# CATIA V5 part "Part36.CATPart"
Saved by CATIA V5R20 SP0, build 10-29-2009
Part number: VA 161320-5
Revision: ANY
Definition: UNKNOWN
Nomenclature: VA 161320-5
Source: Unknown
Bounding box of the stored display mesh (mm): x -6.5 to 6.5, y 0 to 4.2, z -6.337 to 6.337
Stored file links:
  C:\Users\Utente\Desktop\IO LAVORO\3D X SITO CF\CUMSA\3D files VA\VA 201720\Part36.CATPart
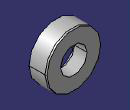
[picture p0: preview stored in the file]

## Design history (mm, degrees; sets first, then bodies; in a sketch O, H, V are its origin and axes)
Body1 "Revolución1" (main body)
  Solid1: solid without history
